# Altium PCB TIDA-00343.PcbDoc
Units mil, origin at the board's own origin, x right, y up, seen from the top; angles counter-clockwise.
Board outline 3150 x 1855.07 mil, 2 copper layers (Top Layer, Bottom Layer), stack 62 mil thick; 23 components, 13 nets, 37 pads, 12 vias.
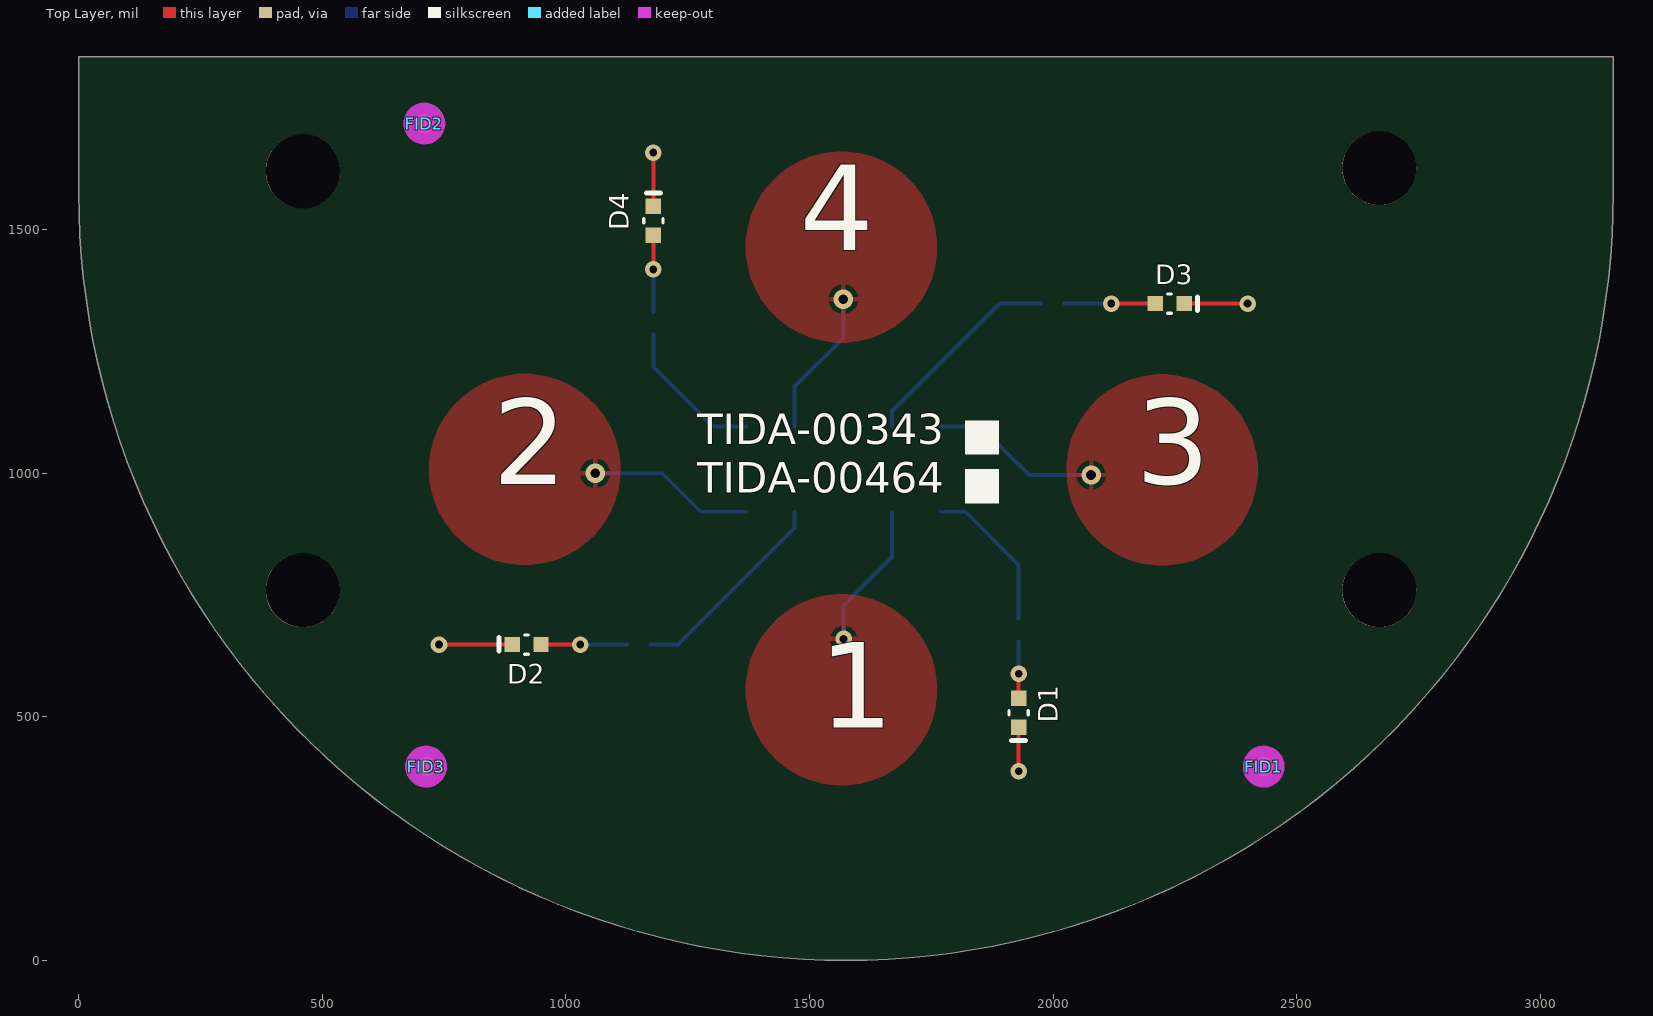
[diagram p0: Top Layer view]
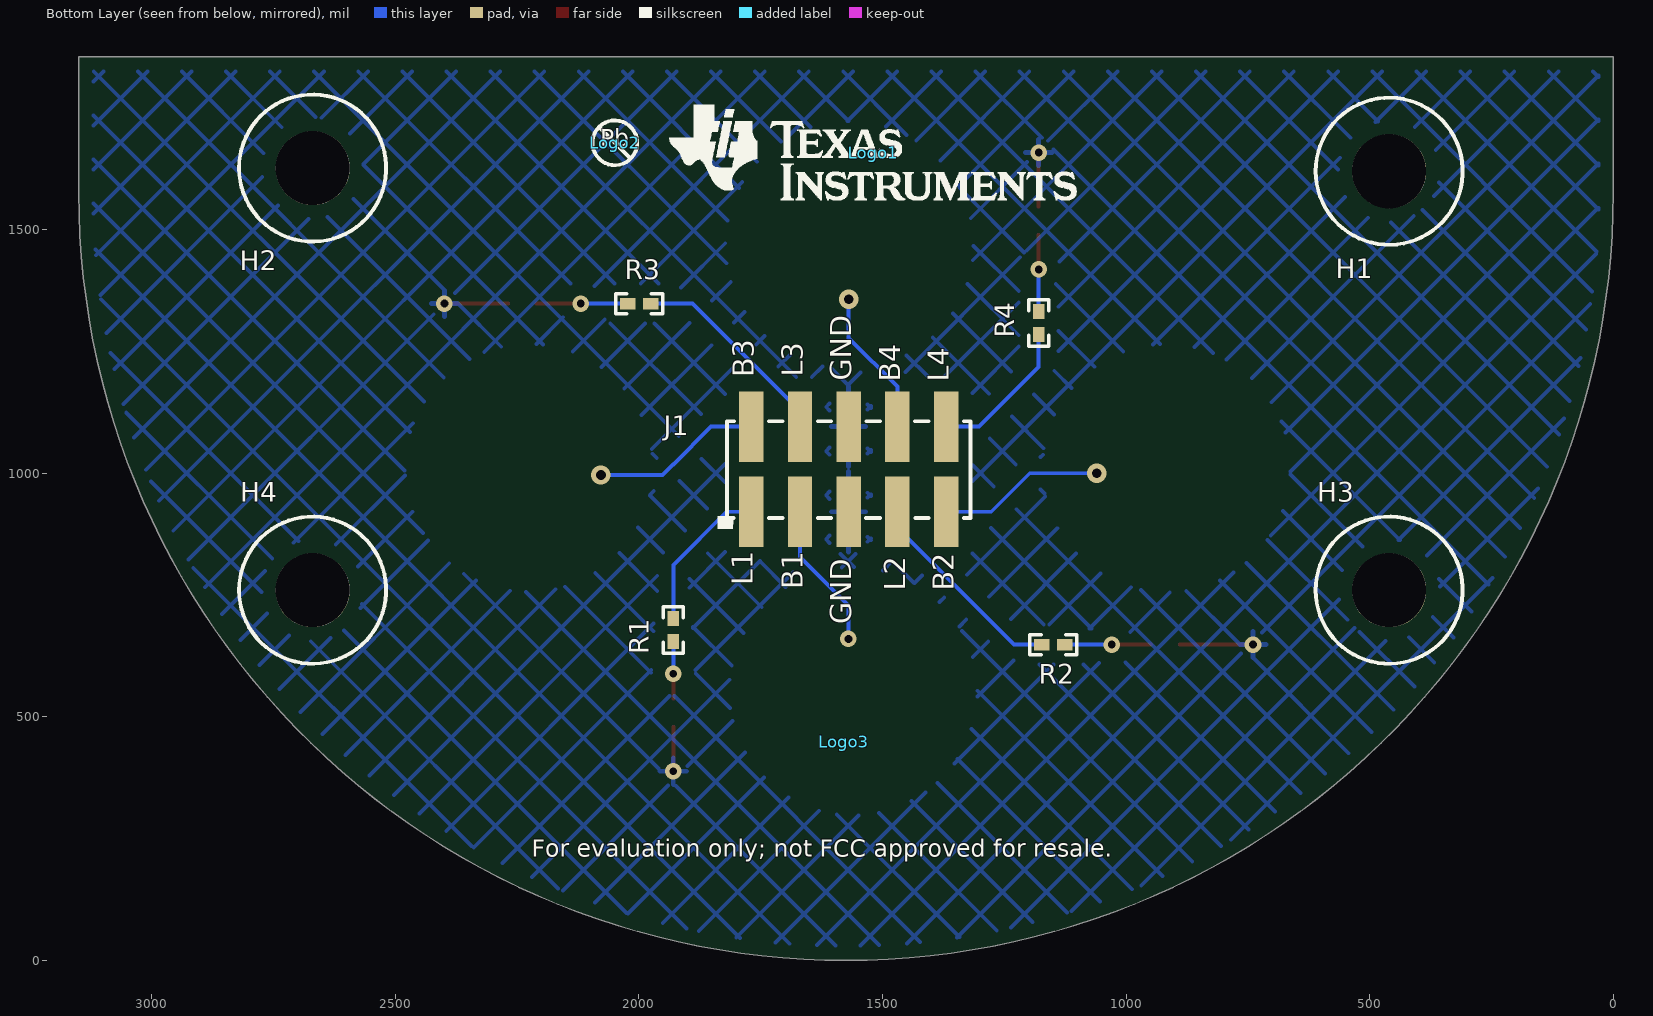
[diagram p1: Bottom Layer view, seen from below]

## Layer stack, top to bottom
Top Solder: solder mask 0.4, Solder Resist, Dk 3.5
Top Layer: signal copper 1.4
Dielectric1: core 59.2, FR-4, Dk 4.8
Bottom Layer: signal copper 1.4
Bottom Solder: solder mask 0.4, Solder Resist, Dk 3.5

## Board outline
0,1575 0,1855 3150,1855 3150,1575 cw(c1575,1574.93)

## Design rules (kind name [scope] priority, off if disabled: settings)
AcuteAngle [All] p1: minimum=4.50000000000000E+0001 checktracksonly=FALSE
AssemblyTestPointUsage [All] p1: valid=2
BoardOutlineClearance BoardOutlineClearance_MountingHoles [OnCopper and InComponentClass('Mounting Holes')] p1: gap=40
BoardOutlineClearance BoardOutlineClearance_Poly [OnCopper and InPoly] p2: gap=25
BoardOutlineClearance [OnCopper and Not InComponentClass('Logo') and not InComponentClass('FiducialMark') and not InRegion(1000,500,4000,800)] p3: gap=25
Clearance Clearance_Keepouts [((IsTrack Or IsArc) And Not InPoly) And IsFree and IsKeepOut vs ((IsTrack Or IsArc) And Not InPoly) And IsFree and IsKeepOut] p1: gap=0
Clearance Clearance_Poly [InPolygon] p2: gap=25
Clearance [All] p3: gap=7.87
ComponentClearance ComponentClearance_MountingHoles_FiducialMarks [InComponentClass('Mounting Holes') vs InComponentClass('FiducialMark')] p1: gap=50 collisioncheckmode=3 verticalgap=10 showdistances=FALSE
ComponentClearance ComponentClearance_Shunt [InComponentClass('Header') vs InComponentClass('Shunt')] p2: gap=0 collisioncheckmode=3 verticalgap=0 showdistances=FALSE
ComponentClearance ComponentClearance_Logo [InComponentClass('Logo')] p3: gap=50 collisioncheckmode=3 verticalgap=10 showdistances=FALSE
ComponentClearance ComponentClearance_ScrewToNut [(HasFootprint('NY PMS 440 0025 PH')) vs (HasFootprint('Keystone_1902C'))] p4: gap=5 collisioncheckmode=3 verticalgap=10 showdistances=FALSE
ComponentClearance ComponentClearance_MountingHoles [InComponentClass('Mounting Holes')] p5: gap=250 collisioncheckmode=3 verticalgap=100000 showdistances=FALSE
ComponentClearance ComponentClearance_SmallPassives [HasFootprint('0201*') or HasFootprint('0402*') or HasFootprint('0508') or HasFootprint('0603*') or HasFootprint('0612') or HasFootprint('0805*') or HasFootprint('0815*') or HasFootprint('0830*') or HasFootprint('1206*') or HasFootprint('1210*') or HasFootprint('1808*') or HasFootprint('1812*') or HasFootprint('1825*') or HasFootprint('2010*') or HasFootprint('2220*') or HasFootprint('2225*') or HasFootprint('2512*') or HasFootprint('2728*') or HasFootprint('3518*') vs HasFootprint('0201*') or HasFootprint('0402*') or HasFootprint('0508') or HasFootprint('0603*') or HasFootprint('0612') or HasFootprint('0805*') or HasFootprint('0815*') or HasFootprint('0830*') or HasFootprint('1206*') or HasFootprint('1210*') or HasFootprint('1808*') or HasFootprint('1812*') or HasFootprint('1825*') or HasFootprint('2010*') or HasFootprint('2220*') or HasFootprint('2225*') or HasFootprint('2512*') or HasFootprint('2728*') or HasFootprint('3518*')] p6: gap=14.96 collisioncheckmode=3 verticalgap=10 showdistances=FALSE
ComponentClearance ComponentClearance_THtoSMT [IsThruComponent vs IsSMTComponent] p7: gap=40 collisioncheckmode=3 verticalgap=30 showdistances=FALSE
ComponentClearance ComponentClearance_THtoTH [IsThruComponent vs IsThruComponent] p8: gap=30 collisioncheckmode=3 verticalgap=30 showdistances=FALSE
ComponentClearance [All] p9: gap=30 collisioncheckmode=3 verticalgap=10 showdistances=FALSE
DiffPairsRouting [All] p1: maxlimit=100 minlimit=10 mostfreqgap=10 toplayer_minwidth=15 toplayer_maxwidth=15 toplayer_prefwidth=15 bottomlayer_minwidth=15 bottomlayer_maxwidth=15 bottomlayer_prefwidth=15 maxuncoupledlength=1000
FabricationTestPointUsage TestPointUsage [All] p1: valid=2 allowmultiple=FALSE
FabricationTestpoint Testpoint [All] p1: side=3 testpointundercomponent=TRUE minsize=40 maxsize=100 preferedsize=60 minholesize=0 maxholesize=40 preferedholesize=32 testpointgrid=1 allowsidetop=TRUE allowsidebottom=TRUE usegrid=TRUE gridtolerance=0.01
FanoutControl Fanout_LCC [IsLCC] p1: bgadir=Out bgaviamode=Centered fanoutstyle=Auto fanoutdirection=Alternating viagrid=1 // Fanout_LCC (Default Rule)
FanoutControl Fanout_BGA [IsBGA] p2: bgadir=Out bgaviamode=Centered fanoutstyle=Auto fanoutdirection=Alternating viagrid=1 // Fanout_BGA (Default Rule)
FanoutControl Fanout_Default [All] p4: bgadir=Out bgaviamode=Centered fanoutstyle=Auto fanoutdirection=Alternating viagrid=1 // Fanout_Default (Default Rule)
FanoutControl Fanout_Small [(CompPinCount < 5)] p5: bgadir=Out bgaviamode=Centered fanoutstyle=Auto fanoutdirection=OutThenIn viagrid=1 // Fanout_Small (Default Rule)
Height [All] p1 off: minheight=0 maxheight=1000 prefheight=500
HoleSize [All] p1: absolutevalues=TRUE maxlimit=251 minlimit=7.87 maxpercent=80.000 minpercent=20.000
MinimumAnnularRing MinimumAnnularRing_ThermalPadVias [IsVia and InAnyComponent] p1: minimumring=5.91
MinimumAnnularRing [All] p2: minimumring=8
MinimumSolderMaskSliver MinimumSolderMaskSliver_Logo [InComponentClass('Logo') vs InComponentClass('Logo')] p1: minsoldermaskwidth=0.7
MinimumSolderMaskSliver [All] p2: minsoldermaskwidth=3.94
PlaneConnect [All] p1: planeconnectstyle=Relief reliefexpansion=10 reliefentries=4 reliefconductorwidth=10 reliefairgap=10
PolygonConnect [All] p1: connectstyle=Relief reliefconductorwidth=10 reliefentries=4 polygonreliefangle="90 Angle" airgapwidth=10
RoutingVias ThermalPadVias [IsVia and InAnyComponent] p1: holewidth=7.87 width=19.68 viastyle="Through Hole" minholewidth=7.87 minwidth=19.68 maxholewidth=12.99 maxwidth=23.62
RoutingVias [All] p2: holewidth=16 width=34 viastyle="Through Hole" minholewidth=7.87 minwidth=26 maxholewidth=40 maxwidth=65
SilkToBoardRegionClearance [Not ((IsComment or IsDesignator) And (Hide <> 'False')) and not InRegion(1000,500,4000,800)] p1:
SilkToSilkClearance SilkToSilkClearance_Pb-FreeLogo [(HasFootprint('Pb-Free_Overlay_Medium') OR HasFootprint('Pb-Free_Overlay_Small')) vs (HasFootprint('Pb-Free_Overlay_Medium') OR HasFootprint('Pb-Free_Overlay_Small'))] p1: silktosilkclearance=0
SilkToSilkClearance [All] p2: silktosilkclearance=4
SilkToSolderMaskClearance SilkToComponentPadClearance [IsPad and InAnycomponent] p1: minsilkscreentomaskgap=5 clearancetoexposedcopper=TRUE
SilkToSolderMaskClearance "Silk to Solder Mask Opening" [All] p2: minsilkscreentomaskgap=4 clearancetoexposedcopper=FALSE
SolderMaskExpansion [All] p1: expansion=1.97
Width [All] p1: maxlimit=100 minlimit=6 preferedwidth=10 checkconnectedcopper=TRUE
14 further rules are at their usual default settings.

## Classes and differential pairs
component class Header: J1
component class PCB_Project_BlankSheet: D1 D2 D3 D4 J1 R1 R2 R3 R4
component class Logo: Logo1
component class PCB_Project_EVM_Hardware: FID1 FID2 FID3 H1 H2 H3 H4 H? Logo1 Logo2 Logo3 ZZ1 ZZ2 ZZ3 ZZ4
component class FiducialMark: FID1 FID2 FID3
component class AssemblyNote: ZZ1 ZZ2 ZZ3 ZZ4

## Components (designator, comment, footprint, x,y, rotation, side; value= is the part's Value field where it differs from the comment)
D1 "LG L29K-G2J1-24-Z" "LG L29K_GREEN" 1929.5,508.35 r270 top
D2 "LG L29K-G2J1-24-Z" "LG L29K_GREEN" 919.5,648.35 r180 top
D3 "LG L29K-G2J1-24-Z" "LG L29K_GREEN" 2239.5,1348.35 r0 top
D4 "LG L29K-G2J1-24-Z" "LG L29K_GREEN" 1179.5,1518.35 r90 top
FID1 "Fiducial" Fiducial10-20 2432.55,397.84 r0 top
FID2 "Fiducial" Fiducial10-20 709.5,1717.84 r0 top
FID3 "Fiducial" Fiducial10-20 712.87,397.84 r0 top
H1 "4826" KEYSTONE_4826 460,1620 r180 bottom
H2 "4826" KEYSTONE_4826 2670,1626.47 r180 bottom
H3 "4826" KEYSTONE_4826 460,760 r180 bottom
H4 "4826" KEYSTONE_4826 2670,760 r180 bottom
J1 "0015910100" Molex_0015910100 1569.5,1008.35 r180 bottom
Logo1 "Texas Instruments" TI_Stacked_Overlay_Small 1519.5,1658.35 r180 bottom
Logo2 "Pb-Free Symbol" Pb-Free_Overlay_Small 2049.5,1678.35 r180 bottom
Logo3 "FCC disclaimer" FCC_disclaimer 1579.5,448.35 r180 bottom
R1 "CRCW0402470RJNED" 0402 1929.5,678.35 r90 bottom
R2 "CRCW0402470RJNED" 0402 1149.5,648.35 r0 bottom
R3 "CRCW0402470RJNED" 0402 1999.5,1348.35 r180 bottom
R4 "CRCW0402470RJNED" 0402 1179.5,1308.35 r270 bottom
ZZ1 "This Assembly Note is for PCB labels only" AssemblyNoteLabel 185,3938 r0 top
ZZ2 "These assemblies are ESD sensitive, ESD precautions shall be observed." AssemblyNote 185,3829.11 r0 top
ZZ3 "These assemblies must be clean and free from flux and all contaminants. Use of no clean flux is not acceptable." AssemblyNote 185,3740.56 r0 top
ZZ4 "These assemblies must comply with workmanship standards IPC-A-610 Class 2, unless otherwise specified." AssemblyNote 185,3652 r0 top

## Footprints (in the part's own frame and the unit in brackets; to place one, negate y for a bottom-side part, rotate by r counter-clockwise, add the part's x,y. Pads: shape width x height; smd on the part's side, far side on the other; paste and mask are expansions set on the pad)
0402 [mm] "0402 from SM-752 data"
  rect 0.8x0.6 smd: 1(-0.6,0) 2(0.6,0)
  silkscreen extent -1.22,-0.52 1.22,0.52, body extent -0.55,-0.3 0.55,0.3, height 0.6
AssemblyNote [mil] "Assembly Note"
AssemblyNoteLabel [mil] "Assembly Note for PCB Labels"
FCC_disclaimer [mil]
Fiducial10-20 [mm]
  round 1 smd mask+0.5: 1(0,0)
  Top Layer keep-out circle w1.178: c0,0 r0.5
KEYSTONE_4826 [mil] "HEX STANDOFF 6-32 NYLON 1750 mil"
  round 1 on Mech4: 0(0,0)
  round 152 hole 152 unplated: MH(0,0)
  silkscreen extent -151,-151 151,151, body extent -144,-125 144,125, height 1751
"LG L29K_GREEN" [mm] "OSRAM"
  rect 0.8x0.8 smd paste-0.4: 1(-0.75,0) 2(0.75,0)
  silkscreen extent -0.1,-0.5 1.45,0.5, body extent -0.9,-0.45 0.9,0.45, height 0.67
Molex_0015910100 [mm] "MOLEX"
  rect 1.27x3.68 smd: 1(-5.08,-2.22) 2(-5.08,2.22) 3(-2.54,-2.22) 4(-2.54,2.22) 5(0,-2.22) 6(0,2.22) 7(2.54,-2.22) 8(2.54,2.22) 9(5.08,-2.22) 10(5.08,2.22)
  silkscreen extent -6.85,-3.13 6.35,2.5, body extent -6.35,-3.49 6.35,3.49, height 9.64
Pb-Free_Overlay_Small [mil]
  silkscreen extent -46,-46 46,46
TI_Stacked_Overlay_Small [mil]
  silkscreen extent -418,-98 418,98

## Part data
D1 D2 D3 D4: "LED, Green, SMD"
FID1 FID2 FID3: "Fiducial mark.  There is nothing to buy or mount."
H1 H2 H3 H4: "HEX STANDOFF 6-32 NYLON 1-3/4\""
J1: "Header, 100mil, 5x2, SMT"
Logo1: library part TI_Logo, "Texas Instrument Corporate Signature"
Logo2: library part Pb-Free
Logo3: library part FCC_disclaimer, "FCC_disclaimer"
R1 R2 R3 R4: "RES, 470, 5%, 0.063 W, 0402"
ZZ1: library part AssemblyNoteLabel
ZZ2 ZZ3 ZZ4: library part AssemblyNote

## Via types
v1: diameter 34, hole 16, Top Layer to Bottom Layer, 9 vias
v2: diameter 40, hole 20, Top Layer to Bottom Layer, 3 vias

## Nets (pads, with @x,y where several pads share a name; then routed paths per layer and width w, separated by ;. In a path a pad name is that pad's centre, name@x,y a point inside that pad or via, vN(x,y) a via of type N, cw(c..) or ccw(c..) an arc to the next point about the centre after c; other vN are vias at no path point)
BUTTON1: J1.3 | length 302.2
  Bottom Layer w8: v1(1570,660) 1570,728.86 1669.49,828.35 J1.3
BUTTON2: J1.9 | length 342.2
  Bottom Layer w8: v2(1060,1000) 1075,1000 1197.85,1000 1276.9,920.95 J1.9
BUTTON3: J1.2 | length 349.7
  Bottom Layer w8: J1.2 1852.09,1095.76 1929.5,1018.35 1930.01,1017.84 1951.41,996.44 v2(2078.1,996.44)
BUTTON4: J1.8 | length 303.1
  Bottom Layer w8: J1.8 1469.49,1177.83 1569.5,1277.84 v2(1569.5,1357.44)
GND: D1.2 D2.2 D3.2 D4.2 J1.5 J1.6 | length 491.9
  Top Layer w8: v1(739.5,648.35) D2.2 ; D4.2 v1(1179.5,1658.35) ; v1@1929.5,378.35 v1(1929.5,388.35) D1.2 ; D3.2 v1(2399.5,1348.35)
NetD1_1: D1.1 R1.1 | length 116.9
  Top Layer w8: D1.1 v1(1929.5,588.35)
  Bottom Layer w8: v1(1929.5,588.35) R1.1
NetD2_1: D2.1 R2.1 | length 176.9
  Top Layer w8: D2.1 v1(1029.5,648.35)
  Bottom Layer w8: v1(1029.5,648.35) R2.1
NetD3_1: D3.1 R3.1 | length 186.9
  Top Layer w8: v1(2119.5,1348.35) D3.1
  Bottom Layer w8: R3.1 v1(2119.5,1348.35)
NetD4_1: D4.1 R4.1 | length 156.9
  Top Layer w8: v1(1179.5,1418.35) D4.1
  Bottom Layer w8: R4.1 v1(1179.5,1418.35)
NetJ1_1: J1.1 R1.2 | length 315
  Bottom Layer w8: J1.1 1820.28,920.95 1929.5,811.74 R1.2
NetJ1_4: J1.4 R3.2 | length 429.8
  Bottom Layer w8: J1.4 1669.49,1127.83 1890.01,1348.35 R3.2
NetJ1_7: J1.7 R2.2 | length 428.7
  Bottom Layer w8: R2.2 1230.01,648.35 1469.49,887.83 J1.7
NetJ1_10: J1.10 R4.2 | length 307.2
  Bottom Layer w8: R4.2 1179.5,1218.35 1302.09,1095.76 J1.10
pads on no net: FID1.1 FID2.1 FID3.1 H1.0 H1.MH H2.0 H2.MH H3.0 H3.MH H4.0 H4.MH

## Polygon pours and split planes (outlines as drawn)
BUTTON1 on Top Layer "TOP_LAYER_BUTTON1_P045" (solid, pour order 45): 1369.68,555.58 ccw(c1565.68,555.58) 1565.68,359.58 ccw(c1565.68,555.58) 1761.68,555.58 ccw(c1565.68,555.58) 1565.68,751.58 ccw(c1565.68,555.58)
BUTTON2 on Top Layer "TOP_LAYER_BUTTON2_P043" (solid, pour order 43): 719.5,1007.84 ccw(c915.5,1007.84) 915.5,811.84 ccw(c915.5,1007.84) 1111.5,1007.84 ccw(c915.5,1007.84) 915.5,1203.84 ccw(c915.5,1007.84)
BUTTON4 on Top Layer "TOP_LAYER_BUTTON4_P041" (solid, pour order 41): 1369.68,1464.42 ccw(c1565.68,1464.42) 1565.68,1268.42 ccw(c1565.68,1464.42) 1761.68,1464.42 ccw(c1565.68,1464.42) 1565.68,1660.42 ccw(c1565.68,1464.42)
BUTTON3 on Top Layer "TOP_LAYER_BUTTON3_P039" (solid, pour order 39): 2027.84,1006.87 ccw(c2223.84,1006.87) 2223.84,810.87 ccw(c2223.84,1006.87) 2419.84,1006.87 ccw(c2223.84,1006.87) 2223.84,1202.87 ccw(c2223.84,1006.87)
GND on Bottom Layer "BOTTOM_LAYER_GND_P035" (hatched 45Degree grid 64 track 8, remove dead copper, pour order 35): 0,-50 2459.48,-50 3470,960.52 3470,2000 0,2000

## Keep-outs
Keep-Out Layer:
  text ".Layer_Name" at 577,-858.49 h60

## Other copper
Top Layer:
  text ".Layer_Name" at 890,-850 h60
Bottom Layer:
  pour cut-out: 1305,552.36 ccw(c1560,552.36) 1560,297.37 ccw(c1560,552.36) 1815,552.36 ccw(c1560,552.36) 1560,807.36 ccw(c1560,552.36)
  pour cut-out: 1312.98,1468.33 ccw(c1567.98,1468.33) 1567.98,1213.33 ccw(c1567.98,1468.33) 1822.98,1468.33 ccw(c1567.98,1468.33) 1567.98,1723.33 ccw(c1567.98,1468.33)
  pour cut-out: 662.46,1010.45 ccw(c917.46,1010.45) 917.46,755.45 ccw(c917.46,1010.45) 1172.46,1010.45 ccw(c917.46,1010.45) 917.46,1265.45 ccw(c917.46,1010.45)
  pour cut-out: 1970.98,1010.99 ccw(c2225.98,1010.99) 2225.98,755.99 ccw(c2225.98,1010.99) 2480.98,1010.99 ccw(c2225.98,1010.99) 2225.98,1265.99 ccw(c2225.98,1010.99)
  pour cut-out: -34060,1505 ccw(c-33810,1505) -33810,1255 ccw(c-33810,1505) -33560,1505 ccw(c-33810,1505) -33810,1755 ccw(c-33810,1505)
  pour cut-out: -33750,575 ccw(c-33500,575) -33500,325 ccw(c-33500,575) -33250,575 ccw(c-33500,575) -33500,825 ccw(c-33500,575)
  text ".Layer_Name" at 800,-860 h60

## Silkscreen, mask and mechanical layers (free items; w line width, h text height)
Top Overlay:
  rectangle: 1819.5,938.35 1889.5,1008.35
  rectangle: 1819.5,1038.35 1889.5,1108.35
  text "4" at 1480,1400 h300
  text "TIDA-00343" at 1269.5,1038.35 h108.27
  text "TIDA-00464" at 1269.5,938.35 h108.27
  text "2" at 850,920 h300
  text "3" at 2170,920 h300
  text "1" at 1520,420 h300
  text ".Layer_Name" at 770,-850 h60
Bottom Overlay:
  text "L3" at 1649.5,1198.35 h72.83 r270
  text "B3" at 1749.5,1197.2 h72.83 r270
  text "GND" at 1550,1190 h72.83 r270
  text "L4" at 1349.5,1188.35 h72.83 r270
  text "B4" at 1449.5,1188.35 h72.83 r270
  text "L1" at 1751.62,770.01 h72.83 r270
  text "B1" at 1649.5,761.68 h72.83 r270
  text "B2" at 1339.5,758.35 h72.83 r270
  text "L2" at 1439.5,758.35 h72.83 r270
  text "GND" at 1550,690 h72.83 r270
  text ".Layer_Name" at 760,-870 h60
Top Paste:
  text ".Layer_Name" at 577,-858.49 h60
Bottom Paste:
  text ".Layer_Name" at 577,-858.49 h60
Top Solder:
  text ".Layer_Name" at 577,-858.49 h60
  text ".Layer_Name" at 577,-858.49 h60
Bottom Solder:
  text ".Layer_Name" at 577,-858.49 h60
Drill Guide:
  text ".Layer_Name" at 577,-858.49 h60
M1 Board Outline:
  the board outline again, w10
  text ".Layer_Name" at 577,-858.49 h60
M2 Board Dimensions:
  rectangle: 0,-275 125,-150
  rectangle: 125,-400 500,-275
  lines w7: 0,-275 1000,-275 ; 125,-400 125,-150 ; 250,-400 250,-150 ; 500,-400 500,-150 ; 750,-400 750,-150 ; 0,-400 1000,-400 1000,-150 0,-150 0,-400
  lines w10: -20,60 0,0 ; -20,1795 0,1855 ; -10,0 10,0 ; -10,1855 10,1855 ; 0,651.58 0,0 ; 0,1203.42 0,1855 ; 20,60 0,0 ; 20,1795 0,1855
  text "1855 (mil)" at 35.99,661.58 h60 r90
  text ".Layer_Name" at 577,-858.49 h60
M3 3D STEP Top:
  text ".Layer_Name" at 577,-858.49 h60
M4 3D STEP Bottom:
  text ".Layer_Name" at 577,-858.49 h60
M5 Assembly Top:
  lines w10: -292,-930.17 6308,-930.17 ; -292,-726.83 6310,-726.83 ; -292,-523.5 -292,-1133.5 3713,-1133.5 6310,-1133.5 6310,-523.5 -291.5,-523.5 -291.5,-1133.5 1284,-1133.5 ; 2173,-1133.5 2173,-523.5 ; 3440,-726.83 3440,-523.5 ; 4280,-726.83 4280,-523.5 ; 4902,-1140 4902,-937.17
  text "COMPONENTS MARKED 'DNP' SHOULD NOT BE POPULATED." at 1153.5,-318.5 h60
  text "ASSEMBLY VARIANT:" at 1153,-434 h60
  text ".VariantName" at 2189,-434 h60
  text "PCB VIEWED FROM TOP SIDE" at -228.5,-655.67 h60
  text "BOARD #:" at 2248,-655.67 h60
  text ".PRJ_Number" at 2793.5,-655.67 h60
  text "REV:" at 3638,-655.67 h60
  text ".PCB_Rev" at 3929.5,-655.67 h60
  text "SVN REV:" at 4476,-655.67 h60
  text ".VersionControl_RevNumber" at 4982,-655.67 h60
  text "TID #:" at 2248,-859 h60
  text ".TID" at 2793.5,-859 h60
  text "PLOT NAME =" at -228.5,-1064.34 h60
  text ".plot_File_Name" at 577,-1064.34 h60
  text "GENERATED    :" at 2250,-1064.34 h60
  text ".Print_Date" at 3119.5,-1064.34 h60
  text ".Print_Time" at 3848.5,-1064.34 h60
  text "TEXAS INSTRUMENTS" at 5113,-1064.34 h60
M6 Assembly Bottom:
  lines w10: -292.5,-727.33 6309.5,-727.33 ; -290.5,-930.67 6309.5,-930.67 ; 1115.5,-1140.5 1115.5,-937.67 ; 1737.5,-727.33 1737.5,-524 ; 2577.5,-727.33 2577.5,-524 ; 3844.5,-1134 3844.5,-524 ; 4733.5,-1134 6309,-1134 6309,-524 -292.5,-524 -292.5,-1134 2304.5,-1134 6309.5,-1134 6309.5,-524
  text "COMPONENTS MARKED 'DNP' SHOULD NOT BE POPULATED." at 6102,-318 h60
  text ".VariantName" at 5058,-434 h60
  text "ASSEMBLY VARIANT:" at 6097,-434 h60
  text ".VersionControl_RevNumber" at 1035.5,-656.17 h60
  text "SVN REV:" at 1541.5,-656.17 h60
  text ".PCB_Rev" at 2088,-656.17 h60
  text "REV:" at 2379.5,-656.17 h60
  text ".PRJ_Number" at 3224,-656.17 h60
  text "BOARD #:" at 3769.5,-656.17 h60
  text "PCB VIEWED FROM BOTTOM SIDE" at 6246,-656.17 h60
  text ".TID" at 3224,-859.5 h60
  text "TID #:" at 3769.5,-859.5 h60
  text "TEXAS INSTRUMENTS" at 904.5,-1064.84 h60
  text ".Print_Time" at 2169,-1064.84 h60
  text ".Print_Date" at 2898,-1064.84 h60
  text "GENERATED    :" at 3767.5,-1064.84 h60
  text ".plot_File_Name" at 5440.5,-1064.84 h60
  text "PLOT NAME =" at 6246,-1064.84 h60
M9 Title Sheet:
  drawing of 57 lines, arcs and shapes, not listed
  text "1" at 739.84,8036.5 h70
  text "2" at 3235.5,8036.5 h70
  text "3" at 5724.84,8036.5 h70
  text "4" at 8231.51,8036.5 h70
  text "5" at 10730.5,8036.5 h70
  text "6" at 13235.5,8036.5 h70
  text "A" at -416.5,6893.5 h70
  text "A" at 14383.5,6893.5 h70
  text "B" at -416.5,4513.5 h70
  text "B" at 14383.5,4513.5 h70
  text "C" at -416.5,2138.5 h70
  text "C" at 14383.5,2138.5 h70
  text "PROJECT TITLE:" at 11343.5,277.5 h45
  text ".PRJ_Title" at 11393.5,144.17 h70
  text "DESIGNED FOR:" at 11343.5,-23.5 h45
  text ".PRJ_Customer" at 11393.5,-163.5 h70
  text "D" at -416.5,-231.5 h70
  text "D" at 14383.5,-231.5 h70
  text "FILE NAME:" at 11343.5,-323.5 h45
  text ".PCB_File_Name_No_Path" at 11393.5,-443.5 h70
  text "Texas Instruments (TI) and/or its licensors do not warrant the accuracy or completeness of this specification" at 6374,-605.34 h45
  text "ENGINEER:" at 11343.5,-613.5 h45
  text "LAYOUT BY:" at 12848.5,-613.5 h45
  text "or any information contained therein. TI and/or its licensors do not warrant that this design will meet" at 6329.01,-718 h45
  text ".PRJ_Engineer" at 11393.5,-768.49 h70
  text ".PCB_Layout" at 12899,-768.49 h70
  text "the specifications, will be suitable for your application or fit for any particular purpose, or will operate in" at 6329.01,-830.67 h45
  text ".Layer_Name" at 577,-858.49 h60
  text "ALTIUM DESIGNER VERSION:" at 12848.5,-923.5 h45
  text "an implementation. TI and/or its licensors do not warrant that the design is production worthy. You should" at 6329.01,-943.33 h45
  text "completely validate and test your design implementation to confirm the system functionality for your application." at 6374,-1056 h45
  text ".print_Scale" at 11393.5,-1056.83 h70
  text ".Application_BuildNumber" at 12899,-1056.83 h70
  text "1" at 739.84,-1263.5 h70
  text "2" at 3235.5,-1263.5 h70
  text "3" at 5724.84,-1263.5 h70
  text "4" at 8231.51,-1263.5 h70
  text "5" at 10730.5,-1263.5 h70
  text "6" at 13235.5,-1263.5 h70
M10 Fab Notes:
  drawing of 173 lines, arcs and shapes, not listed
  text "DESIGN INFORMATION" at 12378.02,6201 h60
  text "MIN. TRACK WIDTH:" at 11733.46,6021 h60
  text "8" at 12829.7,6021 h60
  text "MIL" at 12984.46,6021 h60
  text "MIN. CLEARANCE:" at 11733.46,5889 h60
  text "0.2" at 12769.7,5889 h60
  text "mm" at 12984.46,5889 h60
  text "MIN. VIA PAD SIZE:" at 11733.46,5757 h60
  text "24" at 12799.71,5757 h60
  text "MIL" at 12984.46,5757 h60
  text "0.05mm (2MIL)" at 12428.46,5615.29 h60
  text "MINIMUM ANNULAR RING" at 11404.23,5611 h60
  text "EXTERNAL" at 13136.46,5611 h60
  text "PER" at 11604.23,5493 h60
  text "IPC-D-275 CLASS 2 LEVEL C" at 11824.23,5493 h60
  text "MIL, HOLES" at 13312.46,5380.71 h60
  text "+/-" at 12920,5380 h60
  text "+/-" at 13774,5380 h60
  text "REGISTRATION TOLERANCES:" at 11404.23,5375 h60
  text "METAL" at 12604,5375 h60
  text "5" at 13180.2,5375 h60
  text "3" at 14013.2,5375 h60
  text "MIL" at 14129.46,5375 h60
  text "+/-" at 13774,5262 h60
  text "HOLE SIZE TOLERANCE (UNLESS OTHERWISE SPECIFIED):" at 11404.23,5257 h60
  text "3" at 14013.2,5257 h60
  text "MIL" at 14129.46,5257 h60
  text "MATERIAL:" at 11329.46,5047.54 h60
  text "FR-4 High Tg" at 12315.9,4907.21 h60
  text "FR-408" at 11750.46,4898.64 h60
  text "OTHER" at 13238.46,4898.64 h60
  text "X" at 12161,4895 h60
  text "62 MIL (1.6mm) +/-10%" at 12070.56,4735.92 h60
  text "THICKNESS:" at 11404.23,4731.64 h60
  text "X" at 11942.4,4731.64 h60
  text "OTHER" at 13355.46,4731.64 h60
  text "TOLERANCE:" at 11404.23,4573.64 h60
  text "X" at 12243.53,4573.64 h60
  text "ANSI IPC-6012 TYPE 3 CLASS 2" at 12430.48,4573.64 h60
  text "OTHER +/-" at 12430.46,4417.64 h60
  text "BOW & TWIST:" at 11404.23,4260.64 h60
  text "X" at 12243.53,4260.64 h60
  text "ANSI IPC-6012 TYPE 3 CLASS 2" at 12430.48,4260.64 h60
  text "OTHER +/-" at 12430.46,4102.13 h60
  text "DRILLING:" at 11329.46,3963.64 h60
  text "REFERENCE:" at 11404.23,3846.64 h60
  text "X" at 12052.46,3846.64 h60
  text "AS SHOWN" at 12239.46,3846.64 h60
  text "X" at 12953.46,3846.64 h60
  text "NC_DRILL FILES" at 13090.46,3846.64 h60
  text "PTH MIN COPPER THICKNESS:" at 11404.23,3688.64 h60
  text "X" at 12754.46,3688.64 h60
  text "1MIL" at 12891.46,3688.64 h60
  text "OTHER" at 13388.46,3688.64 h60
  text "BOARD FINISH:" at 11329.46,3529.64 h60
  text "SILKSCREEN:" at 11484.68,3411.64 h60
  text "X" at 12433.46,3411.64 h60
  text "TOP" at 12559.46,3411.64 h60
  text "X" at 12943.46,3411.64 h60
  text "BOTTOM" at 13070.46,3411.64 h60
  text "SILKSCREEN COLOR:" at 11484.68,3244.64 h60
  text "X" at 12432.42,3244.64 h60
  text "WHITE" at 12559.46,3244.64 h60
  text "OTHER" at 13070.46,3244.64 h60
  text "X" at 12563.42,3085.44 h60
  text "GREEN" at 12690.46,3085.44 h60
  text "OTHER" at 13308.46,3085.44 h60
  text "SOLDER RESIST COLOR:" at 11484.68,3074.64 h60
  text "X" at 12563.42,2915.44 h60
  text "MATTE" at 12690.46,2915.44 h60
  text "SEMI-GLOSS" at 13308,2914.8 h60
  text "IMMERSION GOLD (ENIG)" at 12390.46,2726.92 h60
  text "ENEPIG" at 13728,2723.64 h60
  text "SURFACE FINISH:" at 11329.46,2722.64 h60
  text "X" at 12203.51,2722.64 h60
  text "IMM. TIN/SILVER OR EQUIV" at 11659,2565.64 h60
  text "OTHER" at 13090.46,2565.64 h60
  text "ARRAY/PANEL:" at 11329.46,2386.64 h60
  text "CUT AND TRIM PER M1 BOARD OUTLINE" at 12390.46,2382.35 h60
  text "N.C. ROUTE" at 12390.46,2230.64 h60
  text "X" at 13069.46,2230.64 h60
  text "V. SCORE" at 13256.46,2230.64 h60
  text "CERTIFICATION:" at 11329.46,2093.64 h60
  text "MATERIALS AND WORKMANSHIP FOR ALL PCBS" at 12054.46,2093.64 h60
  text "TO MEET OR EXCEED THE REQUIREMENTS OF:" at 12054.46,1995.64 h60
  text "X" at 11680.96,1859.13 h60
  text "ANSI IPC-A-600F CLASS ->" at 11819.96,1859.13 h60
  text "X" at 13459.02,1859.13 h60
  text "2" at 13577.96,1859.14 h60
  text "1" at 13262.96,1857.64 h60
  text "3" at 13931.96,1857.64 h60
  text "X" at 12495.02,1699.64 h60
  text "RoHS" at 12631.96,1699.64 h60
  text "OTHER" at 13276.36,1699.64 h60
  text "PER ORDER" at 13673.42,1699.64 h60
  text "ALL BOARDS MUST MEET OR EXCEED UL94-V0 REQUIREMENTS." at 11357,1534 h60
  text "PCB MUST BEAR THE UL94V-0 UL REGISTERED MATERIAL ID NUMBER" at 11357,1414 h60
  text "ADDITIONAL REQUIREMENTS:" at 11329.46,1240.64 h60
  text "MICROSECTION:" at 11404.23,1125.64 h60
  text "YES" at 12309.96,1125.64 h60
  text "REQUIRED" at 13171.46,969.49 h60
  text "BARE BOARD ELEC. TEST:" at 11404.23,966.64 h60
  text "NONE" at 12709.96,966.64 h60
  text "X" at 13044.46,966.64 h60
  text "PER ORDER" at 13763.46,966.64 h60
  text ".Layer_Name" at 577,-858.49 h60
M11 Gerber Information:
  lines w10: -292,-930.17 6308,-930.17 ; -292,-726.83 6310,-726.83 ; -292,-523.5 -292,-1133.5 3713,-1133.5 6310,-1133.5 6310,-523.5 -291.5,-523.5 -291.5,-1133.5 1284,-1133.5 ; 2173,-1133.5 2173,-523.5 ; 3440,-726.83 3440,-523.5 ; 4280,-726.83 4280,-523.5 ; 4902,-1140 4902,-937.17
  text "ALL ARTWORK VIEWED FROM TOP SIDE" at -228.5,-655.67 h60
  text "BOARD #:" at 2248,-655.67 h60
  text ".PRJ_Number" at 2793.5,-655.67 h60
  text "REV:" at 3638,-655.67 h60
  text ".PCB_Rev" at 3929.5,-655.67 h60
  text "SVN REV:" at 4476,-655.67 h60
  text ".VersionControl_RevNumber" at 4982,-655.67 h60
  text "LAYER NAME =" at -228.5,-858.49 h60
  text "TID #:" at 2248,-859 h60
  text ".TID" at 2793.5,-859 h60
  text "PLOT NAME =" at -228.5,-1064.34 h60
  text ".plot_File_Name" at 577,-1064.34 h60
  text "GENERATED    :" at 2250,-1064.34 h60
  text ".Print_Date" at 3119.5,-1064.34 h60
  text ".Print_Time" at 3848.5,-1064.34 h60
  text "TEXAS INSTRUMENTS" at 5113,-1064.34 h60
M12 Stackup:
  drawing of 191 lines, arcs and shapes, not listed
  text "Layer" at 9790.34,7830 h60
  text "Name" at 10200.26,7830 h60
  text "Material" at 11130,7830 h60
  text "Thickness" at 11989.77,7830 h60
  text "Constant" at 12639.6,7830 h60
  text "Board Layer Stack" at 13209.46,7830 h60
  text "1" at 9790.34,7710 h60
  text "Top Overlay" at 10200.26,7710 h60
  text "2" at 9790.34,7590 h60
  text "Top Solder" at 10200.26,7590 h60
  text "Solder Resist" at 11130,7590 h60
  text "0.40mil" at 11989.77,7590 h60
  text "3.5" at 12639.6,7590 h60
  text "3" at 9790.34,7470 h60
  text "Top Layer" at 10200.26,7470 h60
  text "Copper" at 11130,7470 h60
  text "1.40mil" at 11989.77,7470 h60
  text "4" at 9790.34,7350 h60
  text "Dielectric1" at 10200.26,7350 h60
  text "FR-4" at 11130,7350 h60
  text "59.20mil" at 11989.77,7350 h60
  text "4.8" at 12639.6,7350 h60
  text "5" at 9790.34,7230 h60
  text "Bottom Layer" at 10200.26,7230 h60
  text "Copper" at 11130,7230 h60
  text "1.40mil" at 11989.77,7230 h60
  text "6" at 9790.34,7110 h60
  text "Bottom Solder" at 10200.26,7110 h60
  text "Solder Resist" at 11130,7110 h60
  text "0.40mil" at 11989.77,7110 h60
  text "3.5" at 12639.6,7110 h60
  text "7" at 9790.34,6990 h60
  text "Bottom Overlay" at 10200.26,6990 h60
  text ".Layer_Name" at 577,-858.49 h60
M13 Component Bodies Top:
  text ".Layer_Name" at 577,-858.49 h60
M14 Component Bodies Bottom:
  text ".Layer_Name" at 577,-858.49 h60
M15 Courtyards Top:
  text ".Layer_Name" at 577,-858.49 h60
M16 Courtyards Bottom:
  text ".Layer_Name" at 577,-858.49 h60
Drill Drawing:
  lines w10: 5336.09,2990.02 5363.72,3003.83 5391.34,2990.02 5377.53,3017.64 5391.34,3045.27 5363.72,3031.46 5336.09,3045.27 5349.9,3017.64 5336.09,2990.02 ; 5336.09,3128.15 5349.9,3128.15 5349.9,3114.34 5377.53,3114.34 5377.53,3128.15 5391.34,3128.15 5391.34,3155.78 5377.53,3155.78 5377.53,3169.59 5349.9,3169.59 5349.9,3155.78 5336.09,3155.78 5336.09,3128.15 ; 5336.09,3238.66 5391.34,3238.66 5391.34,3293.91 5336.09,3293.91 5336.09,3238.66
  lines w12: 5286,2952.72 8363.24,2952.72 ; 5286,3325.68 8363.24,3325.68 ; 5623.86,2828.4 5623.86,3450 ; 5955.86,2828.4 5955.86,3450 ; 6592.43,2828.4 6592.43,3450 ; 6851.57,2828.4 6851.57,3450 ; 7226.72,2828.4 7226.72,3450 ; 7951.05,2828.4 7951.05,3450 ; 5286,2828.4 8363.24,2828.4 8363.24,3450 5286,3450 5286,2828.4
  text "Symbol" at 5360.59,3362.98 h72
  text "Quantity" at 5661.16,3362.98 h72
  text "Finished Hole Size" at 5993.16,3362.98 h72
  text "Plated" at 6629.72,3362.98 h72
  text "Hole Type" at 6888.86,3362.98 h72
  text "Drill Layer Pair" at 7264.02,3362.98 h72
  text "Tolerance" at 7988.35,3362.98 h72
  text "4" at 5661.16,3238.66 h60
  text "152.00mil (3.861mm)" at 5993.16,3238.66 h60
  text "NPTH" at 6629.72,3238.66 h60
  text "Round" at 6888.86,3238.66 h60
  text "Top Layer - Bottom Layer" at 7264.02,3238.66 h60
  text "9" at 5661.16,3114.34 h60
  text "16.00mil (0.406mm)" at 5993.16,3114.34 h60
  text "PTH" at 6629.72,3114.34 h60
  text "Round" at 6888.86,3114.34 h60
  text "Top Layer - Bottom Layer" at 7264.02,3114.34 h60
  text "3" at 5661.16,2990.02 h60
  text "20.00mil (0.508mm)" at 5993.16,2990.02 h60
  text "PTH" at 6629.72,2990.02 h60
  text "Round" at 6888.86,2990.02 h60
  text "Top Layer - Bottom Layer" at 7264.02,2990.02 h60
  text "16 Total" at 5661.16,2865.7 h60
  text ".Layer_Name" at 577,-858.49 h60
M17 Embedded Cavity:
  text ".Layer_Name" at 577,-858.49 h60
M18 Embedded Assembly:
  text ".Layer_Name" at 577,-858.49 h60
M19 Embedded Keepout:
  text ".Layer_Name" at 577,-858.49 h60

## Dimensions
0,-400 to 1000,-400 on M2 Board Dimensions
0,0 to 3150,1855 on M2 Board Dimensions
